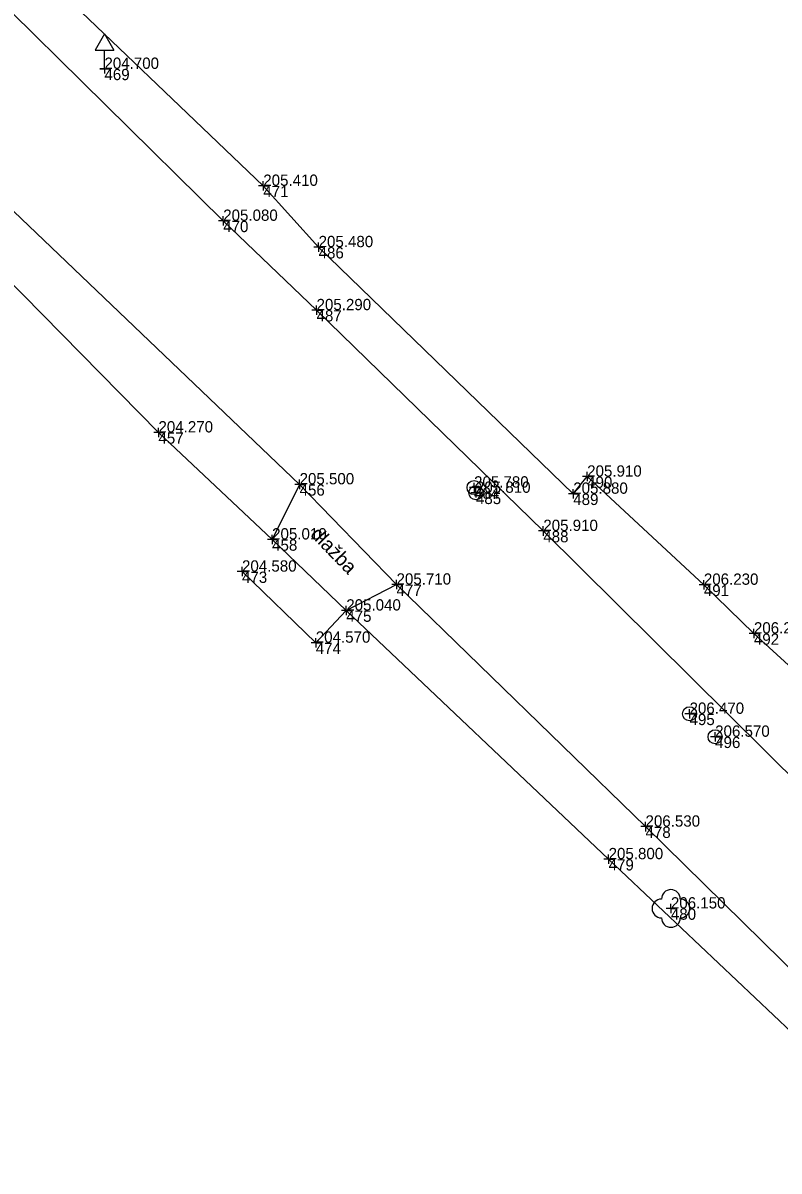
# Model space of a CAD drawing. Extents: x -744883 to -744469, y -966832 to -966374.
# Drawn here: x -744551.5 to -744511.3, y -966811.1 to -966750.1 of the extents above; entities that cross this region are included whole.
import ezdxf

# ---------------------------------------------------------------- set-up
doc = ezdxf.new("R2010")
doc.units = 0
for name, color, linetype in [('Body polohopisu', 7, 'Continuous'), ('Doplňkové značky', 7, 'Continuous'), ('Nezařazené objekty', 7, 'Continuous'), ('Ploty_opěrné zdi', 7, 'Continuous'), ('Popisy objektů_povrchů', 7, 'Continuous'), ('Rozhraní ploch', 7, 'Continuous'), ('Stromy_porost', 7, 'Continuous'), ('Vstup na pozemek', 7, 'Continuous'), ('Výšky bodů', 7, 'Continuous'), ('Značky IS', 7, 'Continuous'), ('Čísla bodů', 7, 'Continuous')]:
    doc.layers.add(name, color=color, linetype=linetype)

msp = doc.modelspace()

# ---------------------------------------------------------------- linework, layer by layer
at = {"layer": 'Body polohopisu'}
for p, q in [((-744547.16, -966752.5), (-744547.16, -966752.25)), ((-744547.16, -966752.5), (-744547.41, -966752.5)), ((-744547.16, -966752.5), (-744546.91, -966752.5)), ((-744547.16, -966752.5), (-744547.16, -966752.75)), ((-744538.72, -966758.72), (-744538.72, -966758.47)), ((-744538.72, -966758.72), (-744538.97, -966758.72)), ((-744538.72, -966758.72), (-744538.47, -966758.72)), ((-744538.72, -966758.72), (-744538.72, -966758.97)), ((-744540.85, -966760.58), (-744540.85, -966760.33)), ((-744540.85, -966760.58), (-744541.1, -966760.58)), ((-744540.85, -966760.58), (-744540.6, -966760.58)), ((-744540.85, -966760.58), (-744540.85, -966760.83)), ((-744535.78, -966761.98), (-744536.03, -966761.98)), ((-744535.78, -966761.98), (-744535.78, -966761.73)), ((-744535.78, -966761.98), (-744535.53, -966761.98)), ((-744535.78, -966761.98), (-744535.78, -966762.23)), ((-744535.89, -966765.33), (-744535.89, -966765.08)), ((-744535.89, -966765.33), (-744536.14, -966765.33)), ((-744535.89, -966765.33), (-744535.64, -966765.33)), ((-744535.89, -966765.33), (-744535.89, -966765.58)), ((-744544.29, -966771.83), (-744544.54, -966771.83)), ((-744544.29, -966771.83), (-744544.29, -966771.58)), ((-744544.29, -966771.83), (-744544.04, -966771.83)), ((-744544.29, -966771.83), (-744544.29, -966772.08)), ((-744536.79, -966774.59), (-744536.79, -966774.34)), ((-744521.51, -966774.18), (-744521.76, -966774.18)), ((-744521.51, -966774.18), (-744521.51, -966773.93)), ((-744521.51, -966774.18), (-744521.26, -966774.18)), ((-744521.51, -966774.18), (-744521.51, -966774.43)), ((-744536.79, -966774.59), (-744537.04, -966774.59)), ((-744536.79, -966774.59), (-744536.54, -966774.59)), ((-744536.79, -966774.59), (-744536.79, -966774.84)), ((-744527.52, -966774.76), (-744527.77, -966774.76)), ((-744527.52, -966774.76), (-744527.52, -966774.51)), ((-744527.52, -966774.76), (-744527.27, -966774.76)), ((-744527.52, -966774.76), (-744527.52, -966775.01)), ((-744527.42, -966775.04), (-744527.42, -966774.79)), ((-744522.25, -966775.09), (-744522.25, -966774.84)), ((-744527.42, -966775.04), (-744527.67, -966775.04)), ((-744527.42, -966775.04), (-744527.17, -966775.04)), ((-744527.42, -966775.04), (-744527.42, -966775.29)), ((-744522.25, -966775.09), (-744522.5, -966775.09)), ((-744522.25, -966775.09), (-744522, -966775.09)), ((-744522.25, -966775.09), (-744522.25, -966775.34)), ((-744523.84, -966777.07), (-744523.84, -966776.82)), ((-744538.25, -966777.52), (-744538.25, -966777.27)), ((-744523.84, -966777.07), (-744524.09, -966777.07)), ((-744523.84, -966777.07), (-744523.59, -966777.07)), ((-744523.84, -966777.07), (-744523.84, -966777.32)), ((-744538.25, -966777.52), (-744538.5, -966777.52)), ((-744538.25, -966777.52), (-744538, -966777.52)), ((-744538.25, -966777.52), (-744538.25, -966777.77)), ((-744539.85, -966779.23), (-744540.1, -966779.23)), ((-744539.85, -966779.23), (-744539.85, -966778.98)), ((-744539.85, -966779.23), (-744539.6, -966779.23)), ((-744539.85, -966779.23), (-744539.85, -966779.48)), ((-744531.64, -966779.92), (-744531.64, -966779.67)), ((-744515.31, -966779.93), (-744515.31, -966779.68)), ((-744531.64, -966779.92), (-744531.89, -966779.92)), ((-744531.64, -966779.92), (-744531.39, -966779.92)), ((-744531.64, -966779.92), (-744531.64, -966780.17)), ((-744515.31, -966779.93), (-744515.56, -966779.93)), ((-744515.31, -966779.93), (-744515.06, -966779.93)), ((-744515.31, -966779.93), (-744515.31, -966780.18)), ((-744534.31, -966781.3), (-744534.31, -966781.05)), ((-744534.31, -966781.3), (-744534.56, -966781.3)), ((-744534.31, -966781.3), (-744534.06, -966781.3)), ((-744534.31, -966781.3), (-744534.31, -966781.55)), ((-744512.65, -966782.52), (-744512.65, -966782.27)), ((-744535.93, -966783.01), (-744535.93, -966782.76)), ((-744512.65, -966782.52), (-744512.9, -966782.52)), ((-744512.65, -966782.52), (-744512.4, -966782.52)), ((-744512.65, -966782.52), (-744512.65, -966782.77)), ((-744535.93, -966783.01), (-744536.18, -966783.01)), ((-744535.93, -966783.01), (-744535.68, -966783.01)), ((-744535.93, -966783.01), (-744535.93, -966783.26)), ((-744516.07, -966786.79), (-744516.07, -966786.54)), ((-744516.07, -966786.79), (-744516.32, -966786.79)), ((-744516.07, -966786.79), (-744515.82, -966786.79)), ((-744516.07, -966786.79), (-744516.07, -966787.04)), ((-744514.71, -966788.01), (-744514.71, -966787.76)), ((-744514.71, -966788.01), (-744514.96, -966788.01)), ((-744514.71, -966788.01), (-744514.46, -966788.01)), ((-744514.71, -966788.01), (-744514.71, -966788.26)), ((-744518.41, -966792.79), (-744518.41, -966792.54)), ((-744518.41, -966792.79), (-744518.66, -966792.79)), ((-744518.41, -966792.79), (-744518.16, -966792.79)), ((-744518.41, -966792.79), (-744518.41, -966793.04)), ((-744520.37, -966794.52), (-744520.62, -966794.52)), ((-744520.37, -966794.52), (-744520.37, -966794.27)), ((-744520.37, -966794.52), (-744520.12, -966794.52)), ((-744520.37, -966794.52), (-744520.37, -966794.77)), ((-744517.06, -966797.14), (-744517.06, -966796.89)), ((-744517.06, -966797.14), (-744517.31, -966797.14)), ((-744517.06, -966797.14), (-744516.81, -966797.14)), ((-744517.06, -966797.14), (-744517.06, -966797.39))]:
    msp.add_line(p, q, dxfattribs=at)
at = {"layer": 'Doplňkové značky'}
for p, q in [((-744547.16, -966750.634), (-744547.66, -966751.5)), ((-744547.16, -966750.634), (-744546.66, -966751.5)), ((-744547.66, -966751.5), (-744546.66, -966751.5)), ((-744547.16, -966752.5), (-744547.16, -966751.5)), ((-744547.41, -966752.5), (-744546.91, -966752.5))]:
    msp.add_line(p, q, dxfattribs=at)
at = {"layer": 'Nezařazené objekty'}
msp.add_lwpolyline([(-744538.25, -966777.52), (-744534.31, -966781.3)], dxfattribs=at)
at = {"layer": 'Ploty_opěrné zdi'}
for points in [[(-744551.22, -966746.76), (-744538.72, -966758.72)], [(-744562.79, -966753.02), (-744544.29, -966771.83)], [(-744535.78, -966761.98), (-744522.25, -966775.09), (-744521.51, -966774.18), (-744515.31, -966779.93)], [(-744538.25, -966777.52), (-744544.29, -966771.83)], [(-744535.93, -966783.01), (-744534.31, -966781.3), (-744520.37, -966794.52)], [(-744512.65, -966782.52), (-744507.17, -966787.54)], [(-744502.84, -966811.1), (-744520.37, -966794.52)]]:
    msp.add_lwpolyline(points, dxfattribs=at)
at = {"layer": 'Rozhraní ploch'}
for points in [[(-744484.45, -966802.29), (-744488.93, -966807.11), (-744494.18, -966806.31), (-744504.16, -966796.59), (-744523.84, -966777.07), (-744535.89, -966765.33), (-744540.85, -966760.58), (-744553.38, -966748.22), (-744567.31, -966735.07), (-744575.15, -966727.6), (-744592.64, -966710.64), (-744593.17, -966705.66)], [(-744584.36, -966750.78), (-744585.27, -966749.34), (-744576.16, -966739.68), (-744573.45, -966739.5), (-744561.19, -966751.3), (-744536.79, -966774.59), (-744538.25, -966777.52)], [(-744536.79, -966774.59), (-744531.64, -966779.92)], [(-744534.31, -966781.3), (-744531.64, -966779.92), (-744518.41, -966792.79), (-744501.85, -966809.07), (-744502.84, -966811.1)]]:
    msp.add_lwpolyline(points, dxfattribs=at)
at = {"layer": 'Stromy_porost'}
msp.add_circle((-744517.06, -966797.14), 0.0005, dxfattribs=at)
for centre, start, end in [((-744517.06, -966796.64), 0, 179.99999), ((-744517.56, -966797.14), 89.99999, 269.99999), ((-744516.56, -966797.14), 270, 89.99999), ((-744517.06, -966797.64), 179.99999, 359.99999)]:
    msp.add_arc(centre, 0.5, start, end, dxfattribs=at)
at = {"layer": 'Vstup na pozemek'}
for points in [[(-744535.78, -966761.98), (-744538.72, -966758.72)], [(-744539.85, -966779.23), (-744535.93, -966783.01)], [(-744515.31, -966779.93), (-744512.65, -966782.52)]]:
    msp.add_lwpolyline(points, dxfattribs=at)
at = {"layer": 'Značky IS'}
for centre in [(-744527.52, -966774.76), (-744527.42, -966775.04), (-744516.07, -966786.79), (-744514.71, -966788.01)]:
    msp.add_circle(centre, 0.375, dxfattribs=at)

# ---------------------------------------------------------------- texts
at = {"layer": 'Popisy objektů_povrchů'}
msp.add_text('dlažba', height=0.75, rotation=314.01601, dxfattribs=at).set_placement((-744536.263, -966777.294))
at = {"layer": 'Výšky bodů'}
for s, p in [('204.700', (-744547.16, -966752.5)), ('205.410', (-744538.72, -966758.72)), ('205.080', (-744540.85, -966760.58)), ('205.480', (-744535.78, -966761.98)), ('205.290', (-744535.89, -966765.33)), ('204.270', (-744544.29, -966771.83)), ('205.910', (-744521.51, -966774.18)), ('205.500', (-744536.79, -966774.59)), ('205.780', (-744527.52, -966774.76)), ('205.810', (-744527.42, -966775.04)), ('205.880', (-744522.25, -966775.09)), ('205.910', (-744523.84, -966777.07)), ('205.010', (-744538.25, -966777.52)), ('204.580', (-744539.85, -966779.23)), ('205.710', (-744531.64, -966779.92)), ('206.230', (-744515.31, -966779.93)), ('205.040', (-744534.31, -966781.3)), ('206.290', (-744512.65, -966782.52)), ('204.570', (-744535.93, -966783.01)), ('206.470', (-744516.07, -966786.79)), ('206.570', (-744514.71, -966788.01)), ('206.530', (-744518.41, -966792.79)), ('205.800', (-744520.37, -966794.52)), ('206.150', (-744517.06, -966797.14))]:
    msp.add_text(s, height=0.6, dxfattribs=at).set_placement(p)
at = {"layer": 'Čísla bodů'}
for s, p in [('469', (-744547.16, -966753.1)), ('471', (-744538.72, -966759.32)), ('470', (-744540.85, -966761.18)), ('486', (-744535.78, -966762.58)), ('487', (-744535.89, -966765.93)), ('457', (-744544.29, -966772.43)), ('490', (-744521.51, -966774.78)), ('456', (-744536.79, -966775.19)), ('484', (-744527.52, -966775.36)), ('485', (-744527.42, -966775.64)), ('489', (-744522.25, -966775.69)), ('488', (-744523.84, -966777.67)), ('458', (-744538.25, -966778.12)), ('473', (-744539.85, -966779.83)), ('477', (-744531.64, -966780.52)), ('491', (-744515.31, -966780.53)), ('475', (-744534.31, -966781.9)), ('492', (-744512.65, -966783.12)), ('474', (-744535.93, -966783.61)), ('495', (-744516.07, -966787.39)), ('496', (-744514.71, -966788.61)), ('478', (-744518.41, -966793.39)), ('479', (-744520.37, -966795.12)), ('480', (-744517.06, -966797.74))]:
    msp.add_text(s, height=0.6, dxfattribs=at).set_placement(p)

doc.saveas('drawing.dxf')
